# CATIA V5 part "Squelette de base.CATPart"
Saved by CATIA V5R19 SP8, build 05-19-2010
Part number: Squelette de base
Publications: "A", "B", "C", "D", "E", "F", "G", "H"
Bounding box of the stored display mesh (mm): x -62 to 39, y -104 to 89, z 0 to 0
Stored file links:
  G:\EU_thinkMotion\CFAO_2010\MMS_groupe3\MMS_groupe3\A reprendre\lpastor\lpastor\Squelette de base.CATPart
  C:\Users\Loïc\Documents\IFMA\Cours 2A\CFAO\Thinkmotion\Fourche avant.CATProduct
  G:\EU_thinkMotion\CFAO_2010\MMS_groupe3\MMS_groupe3\A reprendre\lpastor\lpastor\Squelette.CATProduct
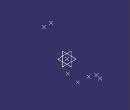
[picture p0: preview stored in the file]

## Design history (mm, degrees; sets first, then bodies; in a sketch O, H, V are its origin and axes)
External parameters (linked from other documents)
  External.Parametre_XA = 0.039
  External.Parametre_YA = 0.068
  External.Parametre_XB = 0
  External.Parametre_YB = 0
  External.Parametre_XC = -0.002
  External.Parametre_YC = 0.076
  External.Parametre_XD = 0.001
  External.Parametre_YD = 0.089
  External.Parametre_XE = 0.032
  External.Parametre_YE = 0.035
  External.Parametre_XF = -0.043
  External.Parametre_YF = -0.103
  External.Parametre_XG = -0.062
  External.Parametre_YG = -0.104
  External.Parametre_XH = 0.012
  External.Parametre_YH = 0.07
Set1 "Set géométrique de base"
  Point1 "A": (39 {= External.Parametre_XA}, 68 {= External.Parametre_YA}, 0)
  Point2 "B": (0 {= External.Parametre_XB}, 0 {= External.Parametre_YB}, 0)
  Point3 "C": (-2 {= External.Parametre_XC}, 76 {= External.Parametre_YC}, 0)
  Point4 "D": (1 {= External.Parametre_XD}, 89 {= External.Parametre_YD}, 0)
  Point5 "E": (32 {= External.Parametre_XE}, 35 {= External.Parametre_YE}, 0)
  Point6 "F": (-43 {= External.Parametre_XF}, -103 {= External.Parametre_YF}, 0)
  Point7 "G": (-62 {= External.Parametre_XG}, -104 {= External.Parametre_YG}, 0)
  Point8 "H": (12 {= External.Parametre_XH}, 70 {= External.Parametre_YH}, 0)
Body1 (main body)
